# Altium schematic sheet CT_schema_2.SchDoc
size 384 x 228 mm
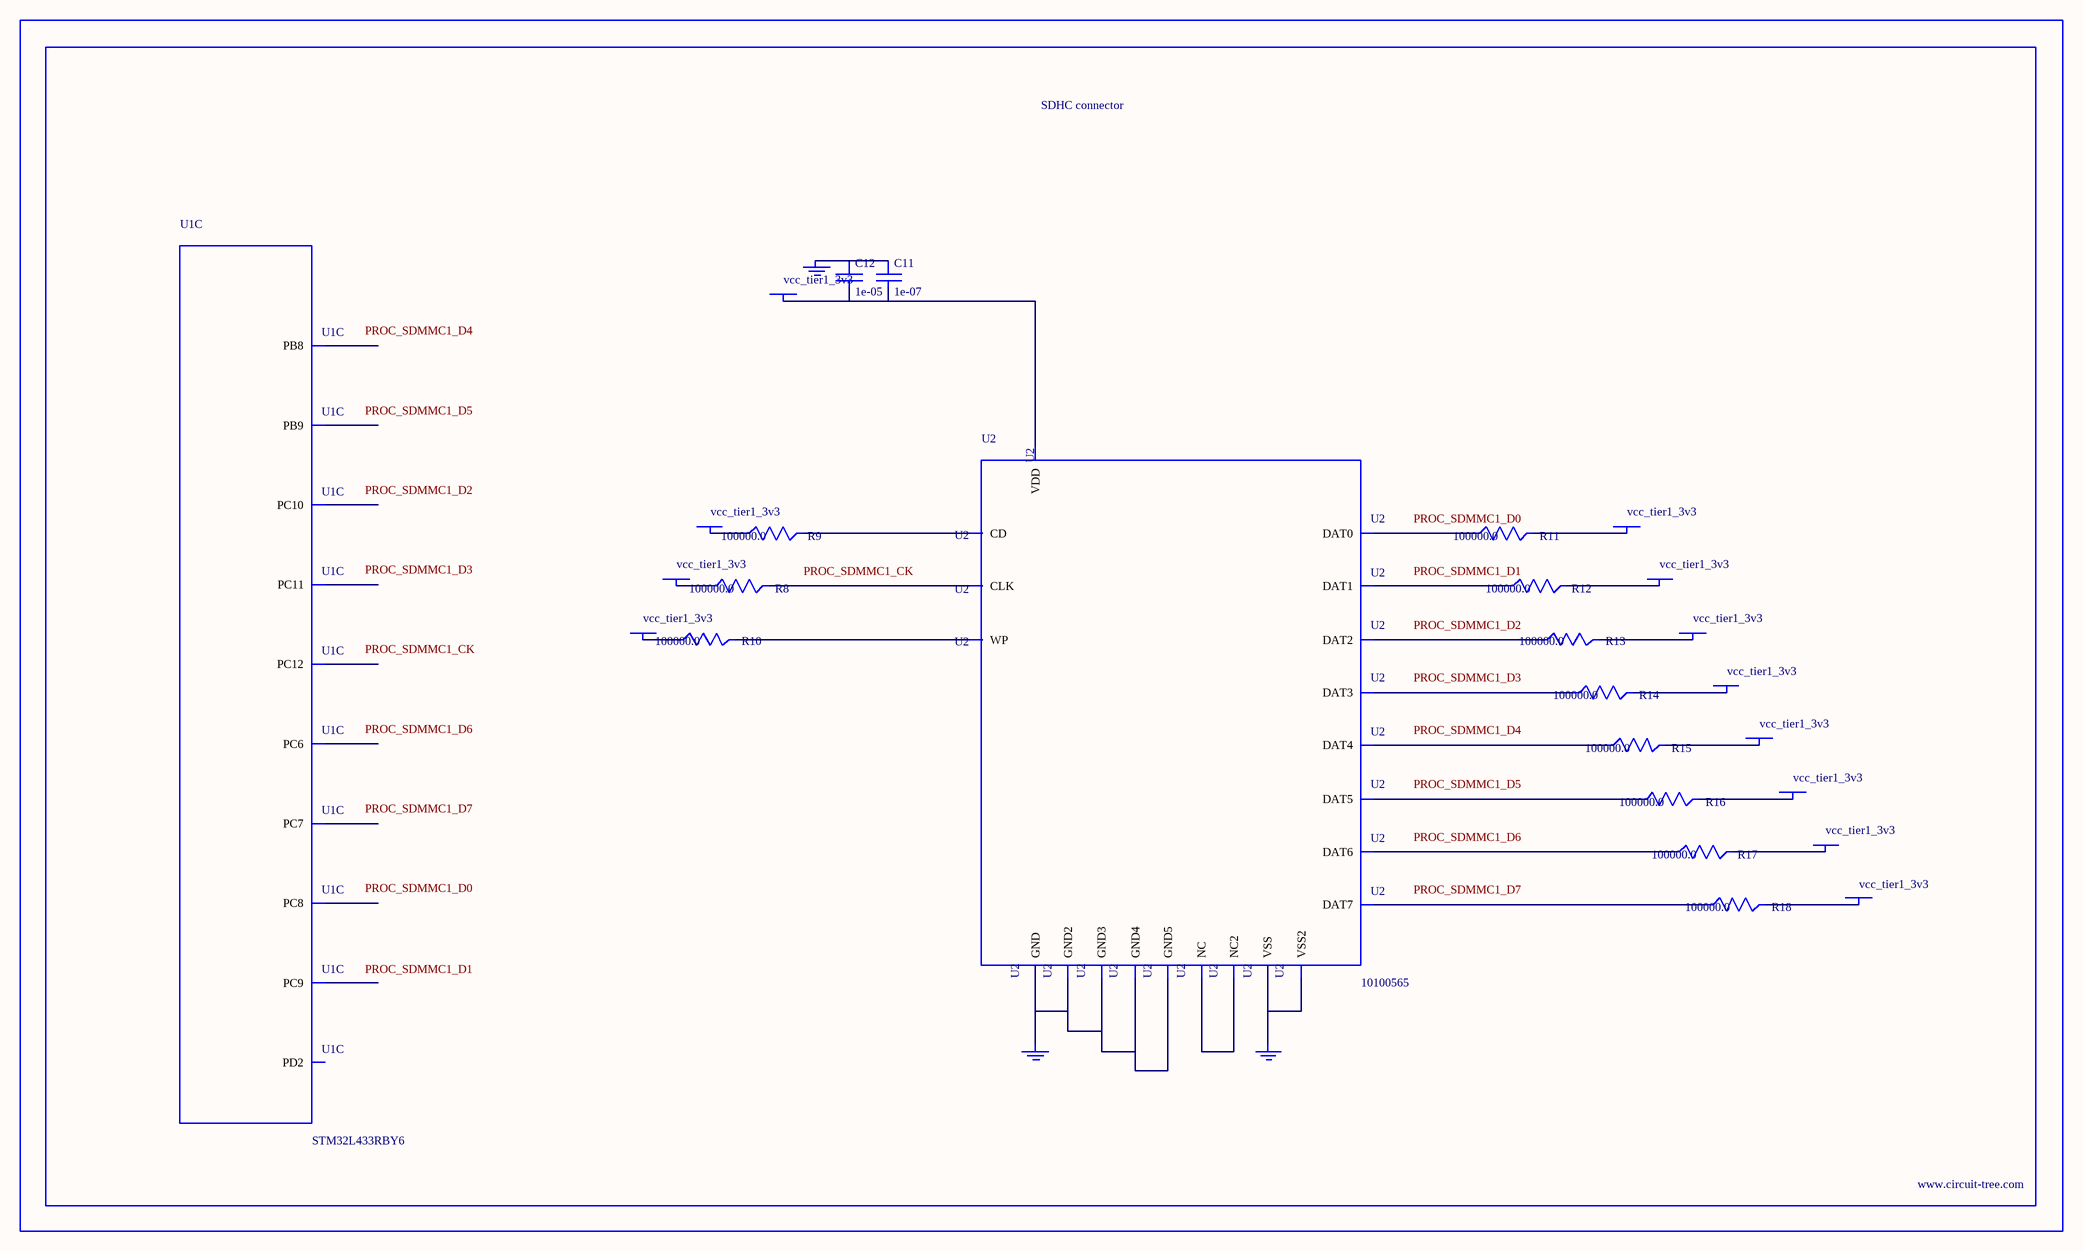
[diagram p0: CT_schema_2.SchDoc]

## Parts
BORDER1  (no value)
C11  1e-07  [C0402]
C12  1e-05  [C0805]
GND_INSTANCE_1_0  (no value)
GND_INSTANCE_1_1  (no value)
GND_INSTANCE_1_2  (no value)
POWER_INSTANCE_1_0  vcc_tier1_3v3
POWER_INSTANCE_1_1  vcc_tier1_3v3
POWER_INSTANCE_1_2  vcc_tier1_3v3
POWER_INSTANCE_1_3  vcc_tier1_3v3
POWER_INSTANCE_1_4  vcc_tier1_3v3
POWER_INSTANCE_1_5  vcc_tier1_3v3
POWER_INSTANCE_1_6  vcc_tier1_3v3
POWER_INSTANCE_1_7  vcc_tier1_3v3
POWER_INSTANCE_1_8  vcc_tier1_3v3
POWER_INSTANCE_1_9  vcc_tier1_3v3
POWER_INSTANCE_1_10  vcc_tier1_3v3
POWER_INSTANCE_1_11  vcc_tier1_3v3
R8  100000.0  [R0603]
R9  100000.0  [R0603]
R10  100000.0  [R0603]
R11  100000.0  [R0603]
R12  100000.0  [R0603]
R13  100000.0  [R0603]
R14  100000.0  [R0603]
R15  100000.0  [R0603]
R16  100000.0  [R0603]
R17  100000.0  [R0603]
R18  100000.0  [R0603]
U1  STM32L433RBY6  [WLCSP64]  (part C of 6)
U2  10100565  [10100565]

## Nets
NetC11_1: C11.1 C12.1 GND_INSTANCE_1_0.0(GND)
NetC11_2: C11.2 C12.2 POWER_INSTANCE_1_7.0(PWR) U2.9(VDD)
NetGND_INSTANCE_1_1_0: GND_INSTANCE_1_1.0(GND) U2.6(VSS) U2.10(VSS2)
NetGND_INSTANCE_1_2_0: GND_INSTANCE_1_2.0(GND) U2.12(GND) U2.16(GND2) U2.17(GND3) U2.20(GND4) U2.21(GND5)
NetPOWER_INSTANCE_1_0_0: POWER_INSTANCE_1_0.0(PWR) R10.1
NetPOWER_INSTANCE_1_1_0: POWER_INSTANCE_1_1.0(PWR) R9.1
NetPOWER_INSTANCE_1_2_0: POWER_INSTANCE_1_2.0(PWR) R12.2
NetPOWER_INSTANCE_1_3_0: POWER_INSTANCE_1_3.0(PWR) R11.2
NetPOWER_INSTANCE_1_4_0: POWER_INSTANCE_1_4.0(PWR) R18.2
NetPOWER_INSTANCE_1_5_0: POWER_INSTANCE_1_5.0(PWR) R17.2
NetPOWER_INSTANCE_1_6_0: POWER_INSTANCE_1_6.0(PWR) R8.1
NetPOWER_INSTANCE_1_8_0: POWER_INSTANCE_1_8.0(PWR) R16.2
NetPOWER_INSTANCE_1_9_0: POWER_INSTANCE_1_9.0(PWR) R15.2
NetPOWER_INSTANCE_1_10_0: POWER_INSTANCE_1_10.0(PWR) R14.2
NetPOWER_INSTANCE_1_11_0: POWER_INSTANCE_1_11.0(PWR) R13.2
NetR8_2: R8.2 U2.8(CLK)
NetR9_2: R9.2 U2.2(CD)
NetR10_2: R10.2 U2.1(WP)
NetR11_1: R11.1 U2.4(DAT0)
NetR12_1: R12.1 U2.3(DAT1)
NetR13_1: R13.1 U2.15(DAT2)
NetR14_1: R14.1 U2.14(DAT3)
NetR15_1: R15.1 U2.13(DAT4)
NetR16_1: R16.1 U2.11(DAT5)
NetR17_1: R17.1 U2.7(DAT6)
NetR18_1: R18.1 U2.5(DAT7)
NetU2_18: U2.18(NC) U2.19(NC2)

Not connected (* = marked no-connect by the designer): U1 A3(PC12) A4(PD2) B3(PC11) B6(PB9) C3(PC10) C6(PB8) E1(PC7) E2(PC9) F1(PC6) F3(PC8)

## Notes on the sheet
- Labels drawn without touching a wire or pin: PROC_SDMMC1_CK, PROC_SDMMC1_D0, PROC_SDMMC1_D1, PROC_SDMMC1_D2, PROC_SDMMC1_D3, PROC_SDMMC1_D4, PROC_SDMMC1_D5, PROC_SDMMC1_D6, PROC_SDMMC1_D7

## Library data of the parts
BORDER1 = BORDER_PAGE1
C11 = C0402C104K3RACTU
C12 = C0805C106K8RACTU
GND_INSTANCE_1_0-GND_INSTANCE_1_2 = GND
POWER_INSTANCE_1_0-POWER_INSTANCE_1_11 = PWR
R8-R18 = RC0603JR-07100KL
